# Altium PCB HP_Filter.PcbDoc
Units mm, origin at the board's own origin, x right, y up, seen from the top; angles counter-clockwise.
Board outline 24.53 x 23.13 mm, 2 copper layers (Top Layer, Bottom Layer); 7 components, 4 nets, 24 pads, 29 vias.
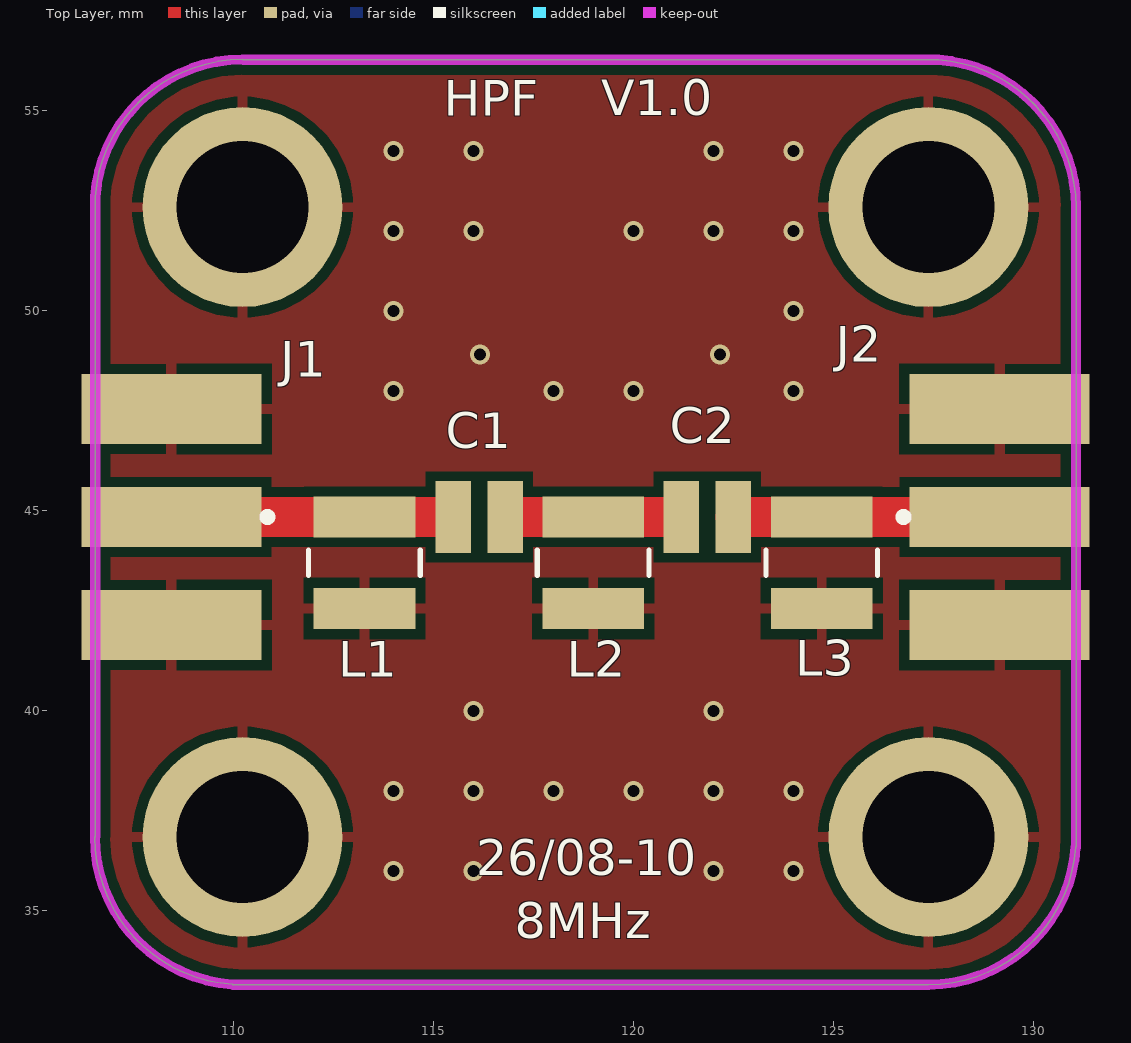
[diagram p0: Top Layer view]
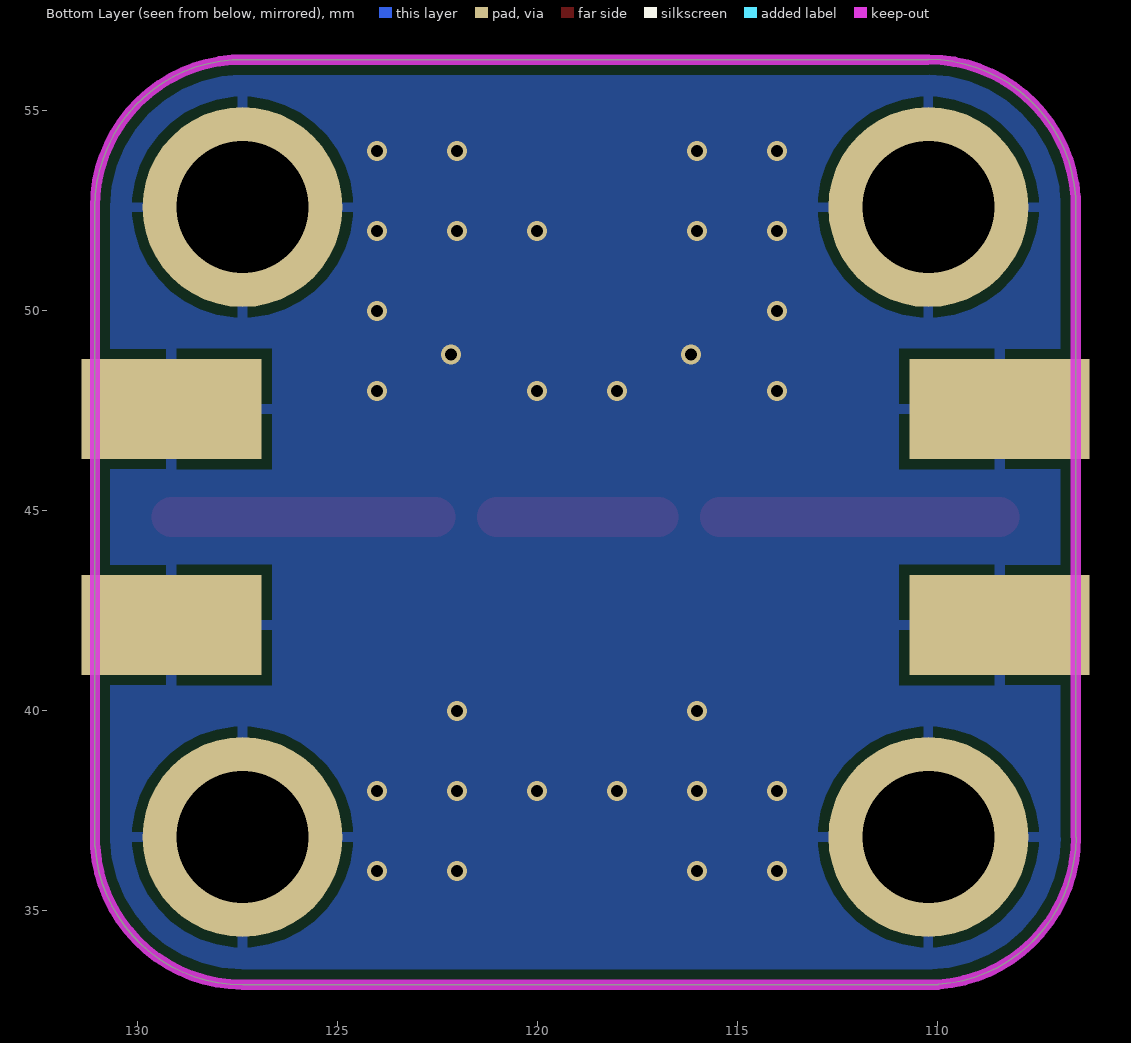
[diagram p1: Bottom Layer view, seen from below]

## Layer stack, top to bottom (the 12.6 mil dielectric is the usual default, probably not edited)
Top Solder: solder mask 0.0102, Solder Resist, Dk 3.5
Top Layer: signal copper 0.0356
Dielectric 1: dielectric 0.32, FR-4, Dk 4.8
Bottom Layer: signal copper 0.0356
Bottom Solder: solder mask 0.0102, Solder Resist, Dk 3.5

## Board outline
109.982,33.147 ccw(c110.003,33.168) 110.003,33.138 127.381,33.138 ccw(c127.381,36.83) 131.064,36.576 ccw(c131.043,36.597) 131.073,36.597 131.073,52.578 ccw(c127.381,52.578) 127.635,56.261 110.257,56.261 cw(c110.257,56.291) 110.236,56.27 ccw(c110.236,52.578) 106.553,52.832 106.553,36.851 cw(c106.523,36.851) 106.544,36.83 ccw(c110.236,36.83)

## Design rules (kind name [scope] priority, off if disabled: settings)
Clearance [All] p1: gap=0.254 ignorepadtopadclearanceinfootprint=FALSE
PolygonConnect [All] p1: thpad.connectstyle=Relief thpad.reliefconductorwidth=0.254 thpad.reliefentries=4 thpad.polygonreliefangle="90 Angle" thpad.airgapwidth=0.254 smdpad.connectstyle=Relief smdpad.reliefconductorwidth=0.254 smdpad.reliefentries=4 smdpad.polygonreliefangle="90 Angle" smdpad.airgapwidth=0.254 via.connectstyle=Direct via.reliefconductorwidth=0.254 via.reliefentries=4 via.polygonreliefangle="90 Angle" via.airgapwidth=0.254
RoutingVias [All] p1: holewidth=0.711 width=1.27 viastyle="Through Hole" minholewidth=0.711 minwidth=1.27 maxholewidth=0.711 maxwidth=1.27
SolderMaskExpansion [All] p1: expansion=0.102 istentingtop=FALSE
Width [All] p1: maxlimit=1 minlimit=0.254 preferedwidth=0.5 minimp=50.000000 maximp=50.000000 favimp=50.000000
30 further rules are at their usual default settings.

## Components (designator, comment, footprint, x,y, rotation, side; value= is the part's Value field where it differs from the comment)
C1 "300pF" CAPC1514X145N 116.15,44.831 r0 top
C2 "300pF" CAPC1514X145N 121.85,44.831 r0 top
J1 "CON-SMA-EDGE-S" RFSOLUTIONS_CON-SMA-EDGE-S 108.458,44.831 r0 top
J2 "CON-SMA-EDGE-S" RFSOLUTIONS_CON-SMA-EDGE-S 129.159,44.831 r180 top
L1 "910" IND_AISC-1008-R12G-T 113.284,43.688 r90 top
L2 "510nH" IND_AISC-1008-R12G-T 118.999,43.688 r90 top
L3 "910" IND_AISC-1008-R12G-T 124.714,43.688 r90 top

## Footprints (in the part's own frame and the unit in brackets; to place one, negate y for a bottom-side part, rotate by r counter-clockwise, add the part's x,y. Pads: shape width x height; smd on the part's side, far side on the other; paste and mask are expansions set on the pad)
CAPC1514X145N [mm]
  rect 0.89x1.79 smd: 1(-0.65,0) 2(0.65,0)
  body extent -0.73,-0.7 0.73,0.7, height 1.45
IND_AISC-1008-R12G-T [mm]
  rect 1.02x2.54 smd: 1(-1.145,0) 2(1.145,0)
  silkscreen extent -0.32,-1.4 0.32,1.4, body extent -1.46,-1.4 1.46,1.4, height 1.62
RFSOLUTIONS_CON-SMA-EDGE-S [mm]
  rect 4.5x1.5 smd: 1(0,0)
  rect 4.5x1.75 smd: G1(0,2.7) G2(0,-2.7)
  rect 4.5x2.5 smd far side: G3(0,2.7) G4(0,-2.7)
  silkscreen extent 2.3,-0.1 2.5,0.1, body extent -11.27,-3.17 2.06,3.17, height 3.55

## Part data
C1 C2: library part 700A301KT150XTV, "Capacitor", Manufacturer_Name="Kyocera AVX"
J1 J2: Package=None
L1 L3: library part AISC-1008-R12G-T, "120 nH Unshielded Drum Core, Wirewound Inductor 650 mA 630mOhm Max 1008 (2520 Metric)", Package="1008 Abracon", Partnumber=AISC-1008-R91G-T
L2: library part AISC-1008-R12G-T, "120 nH Unshielded Drum Core, Wirewound Inductor 650 mA 630mOhm Max 1008 (2520 Metric)", Package="1008 Abracon", Partnumber=AISC-Q0805-R51G-T

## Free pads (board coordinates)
  round 5 hole 3.302 unplated: MH1(110.236,36.83) MH1(110.236,52.578) MH1(127.381,36.83) MH1(127.381,52.578)

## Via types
v1: diameter 0.5, hole 0.3, Top Layer to Bottom Layer, tented both sides, 29 vias

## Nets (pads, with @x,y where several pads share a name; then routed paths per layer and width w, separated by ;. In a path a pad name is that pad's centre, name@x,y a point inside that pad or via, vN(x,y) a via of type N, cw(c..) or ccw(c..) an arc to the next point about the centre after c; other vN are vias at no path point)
NetC1_1: C1.1 J1.1 L1.2 | length 7
  Top Layer w1: J1.1 J1.1 113.664,44.832 113.665,44.833 113.666,44.832 C1.1@115.443,44.832
NetC1_2: C1.2 C2.1 L2.2 | length 4
  Top Layer w1: C1.2@116.982,44.831 116.983,44.832 118.998,44.832 L2.2 119,44.832 121.015,44.832 C2.1@121.016,44.831
NetC2_2: C2.2 J2.1 L3.2 | length 6.6
  Top Layer w1: C2.2@122.555,44.831 124.333,44.831 124.332,44.832 124.333,44.833 124.334,44.832 J2.1 J2.1
NetJ1_G1: J1.G1 J1.G2 J1.G3 J1.G4 J2.G1 J2.G2 J2.G3 J2.G4 L1.1 L2.1 L3.1 pad.MH1
  other v1: 114.015,35.975 116.015,35.975 122.015,35.975 124.015,35.975 114.015,37.975 116.015,37.975 118.015,37.975 120.015,37.975 122.015,37.975 124.015,37.975 116.015,39.975 122.015,39.975 114.015,47.975 118.015,47.975 120.015,47.975 124.015,47.975 116.174,48.895 122.174,48.895 114.015,49.975 124.015,49.975 114.015,51.975 116.015,51.975 120.015,51.975 122.015,51.975 124.015,51.975 114.015,53.975 116.015,53.975 122.015,53.975 124.015,53.975

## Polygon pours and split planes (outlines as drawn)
NetJ1_G1 on Bottom Layer "NETJ1_G1_L02_P001" (solid, pour order 1): 110.236,33.02 129.032,33.02 131.191,35.179 131.191,53.721 128.651,56.261 108.966,56.261 106.68,53.975 106.68,35.179 108.458,33.401
NetJ1_G1 on Top Layer "NETJ1_G1_L01_P000" (solid, pour order 0): 110.109,33.147 128.905,33.147 131.064,35.306 131.064,53.848 128.524,56.388 108.839,56.388 106.553,54.102 106.553,35.306 108.331,33.528

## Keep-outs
Keep-Out Layer:
  the board outline again, w0.2

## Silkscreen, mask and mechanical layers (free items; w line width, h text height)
Top Overlay:
  text "V1.0" at 119.199,54.574 h1.52
  text "HPF" at 115.262,54.556 h1.52
  text "26/08-10" at 116.078,35.578 h1.52
  text "8MHz" at 117.04,34 h1.52
Top Solder:
  drawing of 30 lines, arcs and shapes, not listed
